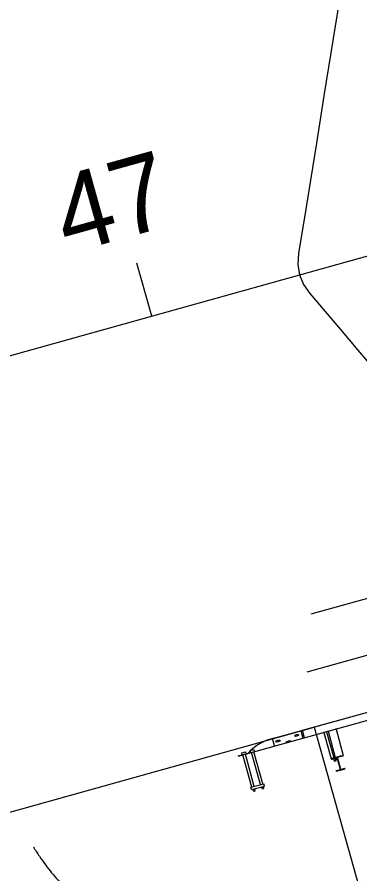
# Model space of a CAD drawing. Extents: x 1512289 to 1544686, y 552531 to 589211.
# Drawn here: x 1543298.38 to 1543310.86, y 587388.14 to 587419.34 of the extents above; entities that cross this region are included whole.
import ezdxf

# ---------------------------------------------------------------- set-up
doc = ezdxf.new("R2010")
doc.units = 0
for name, color, linetype in [('DR_X_Underdrain', 7, 'Continuous'), ('DT_P_Contour_Major', 7, 'Continuous'), ('DT_P_Graded_Shoulder', 7, 'Continuous'), ('DT_P_TIN_Hull', 7, 'Continuous'), ('GE_X_CL_20', 7, 'Continuous'), ('GK_Visualization', 7, 'Continuous'), ('PV_P_EOP', 7, 'Continuous'), ('PV_P_Shoulder', 7, 'Continuous'), ('RD_P_Anchor_Assembly', 7, 'Continuous')]:
    doc.layers.add(name, color=color, linetype=linetype)

msp = doc.modelspace()

# ---------------------------------------------------------------- linework, layer by layer
at = {"layer": 'DR_X_Underdrain'}
msp.add_line((1543343.054, 587405.022), (1543308.934, 587395.488), dxfattribs=at)
at = {"layer": 'DT_P_Contour_Major'}
msp.add_lwpolyline([(1543310.372, 587421.557), (1543309.553, 587416.466), (1543309.277, 587414.743), (1543309.06, 587413.396), (1543308.904, 587412.422), (1543308.631, 587410.726), (1543308.607, 587410.326), (1543308.667, 587409.95), (1543308.811, 587409.597), (1543309.038, 587409.267), (1543310.151, 587407.958), (1543310.789, 587407.207), (1543311.673, 587406.166)], dxfattribs=at)
at = {"layer": 'DT_P_Graded_Shoulder'}
msp.add_open_spline([(1543298.98, 587389.109), (1543301.641, 587384.868), (1543310.813, 587387.706), (1543331.265, 587394.804), (1543350.964, 587398.438), (1543357.632, 587399.75)], degree=2, dxfattribs=at)
at = {"layer": 'DT_P_TIN_Hull'}
msp.add_lwpolyline([(1543344.96, 587445.079), (1543316.658, 587453.481), (1543288.465, 587467.688), (1543299.511, 587428.154), (1543300.587, 587424.305), (1543276.509, 587417.577), (1543280.815, 587402.167), (1543285.12, 587386.758), (1543309.198, 587393.485), (1543310.807, 587387.726), (1543315.282, 587371.713), (1543332.289, 587397.538), (1543358.059, 587398.222)], dxfattribs=at)
at = {"layer": 'GE_X_CL_20'}
for p, q in [((1541212.248, 586824.181), (1543339.287, 587418.505)), ((1543303.284, 587408.446), (1543302.746, 587410.372))]:
    msp.add_line(p, q, dxfattribs=at)
at = {"layer": 'GK_Visualization'}
msp.add_line((1541212.248, 586824.181), (1543339.287, 587418.505), dxfattribs=at)
at = {"layer": 'PV_P_EOP'}
msp.add_line((1543309.092, 587397.609), (1543342.516, 587406.948), dxfattribs=at)
at = {"layer": 'PV_P_Shoulder'}
msp.add_line((1543308.766, 587393.364), (1543343.593, 587403.096), dxfattribs=at)
at = {"layer": 'RD_P_Anchor_Assembly'}
for p, q in [((1543307.553, 587393.029), (1543332.773, 587400.007)), ((1543306.432, 587392.427), (1543332.848, 587399.736)), ((1543308.706, 587393.348), (1543308.781, 587393.077)), ((1543308.841, 587393.093), (1543308.766, 587393.364)), ((1543308.766, 587393.364), (1543308.766, 587393.364)), ((1543309.549, 587393.279), (1543309.814, 587392.322)), ((1543309.556, 587393.291), (1543309.978, 587393.408)), ((1543309.642, 587393.315), (1543309.906, 587392.361)), ((1543309.702, 587393.332), (1543309.966, 587392.378)), ((1543309.991, 587393.401), (1543310.256, 587392.444)), ((1543307.758, 587392.794), (1543307.683, 587393.065)), ((1543306.43, 587392.435), (1543306.794, 587392.536)), ((1543306.528, 587392.453), (1543306.525, 587392.462)), ((1543306.528, 587392.453), (1543306.528, 587392.453)), ((1543306.927, 587391.299), (1543306.602, 587392.474)), ((1543307.017, 587391.324), (1543306.692, 587392.499)), ((1543307.237, 587391.385), (1543306.911, 587392.561)), ((1543307.328, 587391.41), (1543307.004, 587392.579)), ((1543309.826, 587392.315), (1543309.863, 587392.325)), ((1543309.857, 587392.348), (1543310.205, 587392.444)), ((1543309.857, 587392.348), (1543309.863, 587392.325)), ((1543309.864, 587392.331), (1543309.867, 587392.317)), ((1543309.868, 587392.317), (1543310.018, 587392.359)), ((1543309.873, 587392.352), (1543310.189, 587392.44)), ((1543309.878, 587392.335), (1543309.873, 587392.352)), ((1543309.878, 587392.335), (1543310.029, 587392.377)), ((1543309.895, 587392.324), (1543309.909, 587392.277)), ((1543309.939, 587392.24), (1543309.906, 587392.361)), ((1543309.999, 587392.257), (1543309.966, 587392.378)), ((1543309.99, 587392.351), (1543310.003, 587392.303)), ((1543310.014, 587392.373), (1543310.018, 587392.359)), ((1543310.151, 587391.937), (1543310.029, 587392.377)), ((1543310.043, 587392.381), (1543310.194, 587392.422)), ((1543310.164, 587391.941), (1543310.043, 587392.381)), ((1543310.194, 587392.422), (1543310.189, 587392.44)), ((1543310.205, 587392.444), (1543310.211, 587392.421)), ((1543310.211, 587392.421), (1543310.249, 587392.432)), ((1543309.922, 587392.267), (1543309.997, 587392.287)), ((1543309.939, 587392.24), (1543309.999, 587392.257)), ((1543309.999, 587391.896), (1543310.151, 587391.937)), ((1543310.004, 587391.878), (1543309.999, 587391.896)), ((1543310.004, 587391.878), (1543310.32, 587391.966)), ((1543310.164, 587391.941), (1543310.316, 587391.983)), ((1543310.32, 587391.966), (1543310.316, 587391.983)), ((1543306.894, 587391.29), (1543307.36, 587391.419)), ((1543307.383, 587391.335), (1543307.36, 587391.419)), ((1543306.918, 587391.206), (1543306.894, 587391.29)), ((1543306.918, 587391.206), (1543307.383, 587391.335))]:
    msp.add_line(p, q, dxfattribs=at)
for points in [[(1543306.89, 587392.554), (1543306.87, 587392.625), (1543307.004, 587392.662), (1543307.023, 587392.591)], [(1543306.58, 587392.477), (1543306.563, 587392.539), (1543306.696, 587392.576), (1543306.713, 587392.514)], [(1543307.027, 587391.236), (1543307.037, 587391.199), (1543306.971, 587391.18), (1543306.96, 587391.218)], [(1543307.025, 587391.195), (1543307.039, 587391.145), (1543307, 587391.134), (1543306.986, 587391.185)], [(1543307.338, 587391.322), (1543307.347, 587391.287), (1543307.281, 587391.268), (1543307.271, 587391.304)], [(1543307.336, 587391.284), (1543307.35, 587391.232), (1543307.311, 587391.221), (1543307.296, 587391.273)]]:
    msp.add_lwpolyline(points, dxfattribs=at)
for centre, radius, start, end in [((1543309.559, 587393.282), 0.01, 105.4656, 195.4656), ((1543309.981, 587393.398), 0.01, 15.4656, 105.4656), ((1543308.132, 587391.307), 1.817, 102.3439, 137.4206), ((1543309.823, 587392.325), 0.01, 195.4656, 285.4656), ((1543310.246, 587392.441), 0.01, 285.4656, 15.4656)]:
    msp.add_arc(centre, radius, start, end, dxfattribs=at)
for centre, major_axis, ratio in [((1543307.882, 587392.973), (0.08, 0.0221), 0.392116), ((1543308.56, 587393.178), (0.0741, 0.0205), 0.423485)]:
    msp.add_ellipse(centre, major_axis=major_axis, ratio=ratio, dxfattribs=at)
for centre, major_axis, ratio, start_param, end_param in [((1543308.26, 587392.935), (0.1, 0.028), 0.312583, 6.203436, 9.504527), ((1543309.991, 587392.3), (-0.0037, 0.0134), 0.929688, 3.385779, 4.696983), ((1543309.921, 587392.28), (-0.0037, 0.0134), 0.929688, 1.560203, 2.937581)]:
    msp.add_ellipse(centre, major_axis=major_axis, ratio=ratio, start_param=start_param, end_param=end_param, dxfattribs=at)

# ---------------------------------------------------------------- texts
at = {"layer": 'GE_X_CL_20'}
msp.add_text('47', height=2.8, rotation=15.6111, dxfattribs=at).set_placement((1543300.205, 587410.7))

doc.saveas('drawing.dxf')
